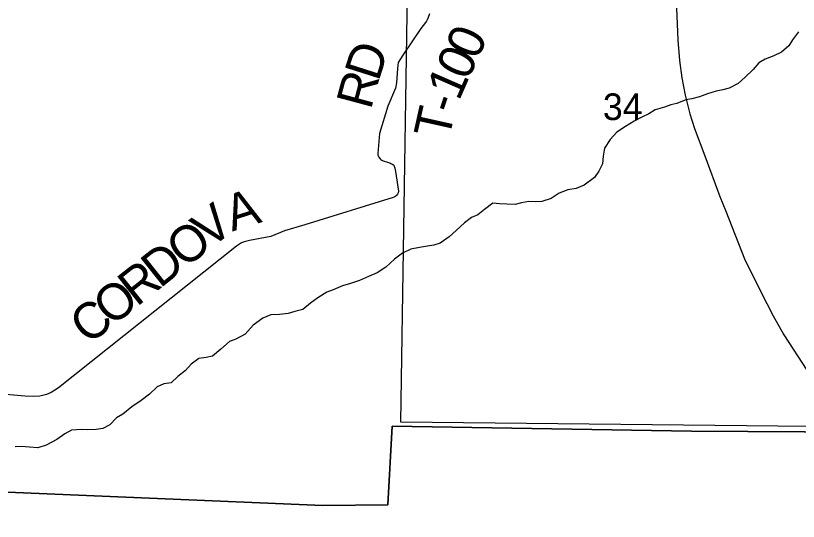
# Model space of a CAD drawing. Extents: x -7.1 to 34, y 0 to 22.
# Drawn here: x 3.24 to 4.468, y 17.646 to 18.44 of the extents above; entities that cross this region are included whole.
import ezdxf

# ---------------------------------------------------------------- set-up
doc = ezdxf.new("R2010")
doc.units = 0
for name, color, linetype in [('GM_X_Minor_River', 7, 'Continuous'), ('GM_X_Section', 7, 'Continuous'), ('GM_X_Section_Text', 7, 'Continuous'), ('GM_X_State_Route', 7, 'Continuous'), ('GM_X_Township_Road', 7, 'Continuous'), ('GM_X_Township_Road_Text', 7, 'Continuous'), ('SH_Cut_Line', 7, 'Continuous')]:
    doc.layers.add(name, color=color, linetype=linetype)

msp = doc.modelspace()

# ---------------------------------------------------------------- linework, layer by layer
at = {"layer": 'GM_X_Minor_River'}
for points in [[(4.4682, 18.4143), (4.4588, 18.4017), (4.4528, 18.3922), (4.4411, 18.3822), (4.4294, 18.3764), (4.4158, 18.3713), (4.4055, 18.3656), (4.3969, 18.3552), (4.3841, 18.3434), (4.3732, 18.3334), (4.3592, 18.3257), (4.3493, 18.3233), (4.3387, 18.3213), (4.3254, 18.3171), (4.3129, 18.3124), (4.3008, 18.3093), (4.2913, 18.3077), (4.2773, 18.3018), (4.2679, 18.2995), (4.2576, 18.296), (4.2432, 18.2917), (4.2334, 18.2855), (4.2224, 18.2805), (4.21, 18.2739), (4.1963, 18.2658), (4.1828, 18.257), (4.1726, 18.2451), (4.1636, 18.2318), (4.1614, 18.2189), (4.1604, 18.2071), (4.1548, 18.1956), (4.1477, 18.1857), (4.1318, 18.1738), (4.1189, 18.1684), (4.106, 18.1664), (4.0924, 18.1609), (4.0799, 18.1529), (4.0652, 18.1482), (4.0557, 18.1473), (4.0447, 18.148), (4.0333, 18.1456), (4.0234, 18.1433), (4.0105, 18.1435), (3.9987, 18.1442), (3.9885, 18.1452), (3.9753, 18.1353), (3.9647, 18.1272), (3.9548, 18.1229), (3.9439, 18.1145), (3.9311, 18.1026), (3.9198, 18.0927), (3.9058, 18.0823), (3.896, 18.0792), (3.8857, 18.0779), (3.8732, 18.0759), (3.8599, 18.0732), (3.8467, 18.067), (3.8342, 18.0574), (3.8207, 18.0447), (3.8071, 18.0359), (3.7934, 18.0301), (3.7791, 18.0239), (3.7651, 18.0192), (3.7525, 18.0153), (3.7378, 18.0091), (3.7279, 18.0056), (3.714, 17.9967), (3.7026, 17.9883), (3.6902, 17.9783), (3.6777, 17.9752), (3.6671, 17.972), (3.6538, 17.9704), (3.6401, 17.9699), (3.6273, 17.9645), (3.6122, 17.9537), (3.5997, 17.9396), (3.5854, 17.9318), (3.5751, 17.9283), (3.5616, 17.9161), (3.5484, 17.9049), (3.5385, 17.903), (3.5271, 17.9014), (3.515, 17.8925), (3.506, 17.8826), (3.4943, 17.873), (3.4838, 17.8634)], [(3.4838, 17.8634), (3.4724, 17.8614), (3.4618, 17.8567), (3.4497, 17.8456), (3.4369, 17.8357), (3.4222, 17.8257), (3.4078, 17.8141), (3.398, 17.8084), (3.3875, 17.7973), (3.3765, 17.7915), (3.3663, 17.7899), (3.3526, 17.7894), (3.3431, 17.7897), (3.3275, 17.7891), (3.3169, 17.783), (3.3045, 17.7745), (3.2878, 17.7656), (3.2746, 17.7614), (3.2617, 17.762), (3.2487, 17.763), (3.2389, 17.7626)]]:
    msp.add_lwpolyline(points, dxfattribs=at)
at = {"layer": 'GM_X_Section'}
msp.add_lwpolyline([(3.8597, 18.828), (4.6987, 18.8125), (4.6817, 17.7925), (3.8439, 17.8017), (3.8583, 18.7127)], close=True, dxfattribs=at)
at = {"layer": 'GM_X_State_Route'}
msp.add_lwpolyline([(4.2752, 18.4883), (4.2777, 18.427), (4.2786, 18.4011), (4.2812, 18.3691), (4.2851, 18.3419), (4.2904, 18.3149), (4.2973, 18.2856), (4.3049, 18.2625), (4.3209, 18.2197), (4.3448, 18.1556), (4.354, 18.1326), (4.3834, 18.058), (4.4082, 18.007), (4.428, 17.9686), (4.4452, 17.9387), (4.4811, 17.883)], dxfattribs=at)
at = {"layer": 'GM_X_Township_Road'}
for points in [[(3.0659, 17.6986), (3.7215, 17.6707), (3.8238, 17.6717), (3.8304, 17.7952), (4.3, 17.7873), (4.5657, 17.7857), (4.7094, 17.7848), (5.0443, 17.7832), (5.0544, 17.7831), (5.1115, 17.7819), (5.5047, 17.7737), (5.7514, 17.7685), (6.1904, 17.7592), (6.3575, 17.7557), (6.7118, 17.7486), (6.7254, 18.1319), (6.7433, 18.7732), (6.7479, 19.0295), (6.7613, 19.7723), (6.7882, 20.743), (6.7921, 20.9), (2.1, 20.9)], [(3.8889, 18.4424), (3.887, 18.437), (3.8854, 18.4334), (3.8843, 18.4312), (3.8827, 18.4291), (3.8755, 18.4196), (3.8473, 18.3776), (3.8399, 18.3661), (3.8389, 18.3566), (3.8374, 18.3345), (3.8356, 18.3257), (3.8235, 18.2978), (3.8105, 18.2546), (3.808, 18.2234), (3.8082, 18.2207), (3.8085, 18.2197), (3.8095, 18.2177), (3.8116, 18.215), (3.8125, 18.2141), (3.8143, 18.2128), (3.8162, 18.2117), (3.8229, 18.2096), (3.8249, 18.2091)], [(3.8249, 18.2091), (3.8268, 18.2085), (3.8286, 18.2078), (3.83, 18.207), (3.8314, 18.2061), (3.8324, 18.2053), (3.8329, 18.2047), (3.8334, 18.204), (3.8338, 18.2032), (3.8347, 18.2002), (3.8356, 18.1953), (3.8403, 18.1642), (3.8398, 18.1618), (3.8388, 18.1593), (3.8374, 18.1572), (3.8349, 18.1555), (3.8321, 18.1542), (3.6937, 18.1111), (3.6615, 18.1018), (3.64, 18.093), (3.6065, 18.0867), (3.5982, 18.0847), (3.5943, 18.083), (3.5861, 18.0776), (3.3072, 17.8556), (3.2952, 17.8478), (3.2882, 17.8448), (3.2821, 17.8433), (3.2776, 17.8422), (3.2675, 17.8416), (3.2545, 17.8421), (3.1086, 17.855)], [(6.7058, 17.2839), (6.7118, 17.7486), (6.3575, 17.7557), (6.1904, 17.7592), (5.7514, 17.7685), (5.5047, 17.7737), (5.1115, 17.7819), (5.0544, 17.7831), (5.0443, 17.7832), (4.7094, 17.7848), (4.5657, 17.7857), (4.3, 17.7873), (3.8304, 17.7952), (3.8238, 17.6717), (3.7215, 17.6707), (3.0659, 17.6986), (2.7886, 17.7105), (2.5551, 17.7155), (2.1, 17.7253), (2.1, 14.1)]]:
    msp.add_lwpolyline(points, dxfattribs=at)
at = {"layer": 'SH_Cut_Line'}
for points in [[(8.9, 17.7079), (8.9, 20.9), (2.1, 20.9), (2.1, 17.7253), (2.5551, 17.7155), (2.7886, 17.7105), (3.0659, 17.6986), (3.7215, 17.6707), (3.8238, 17.6717), (3.8304, 17.7952), (4.3, 17.7873), (4.5657, 17.7857), (4.7094, 17.7848), (5.0443, 17.7832), (5.0544, 17.7831), (5.1115, 17.7819), (5.5047, 17.7737), (5.7514, 17.7685), (6.1904, 17.7592), (6.3575, 17.7557), (6.7118, 17.7486), (7.7202, 17.7285), (8.4472, 17.7189), (8.6668, 17.7136)], [(2.1, 17.7253), (2.1, 14.1), (8.9, 14.1), (8.9, 17.7079), (8.6668, 17.7136), (8.4472, 17.7189), (7.7202, 17.7285), (6.7118, 17.7486), (6.3575, 17.7557), (6.1904, 17.7592), (5.7514, 17.7685), (5.5047, 17.7737), (5.1115, 17.7819), (5.0544, 17.7831), (5.0443, 17.7832), (4.7094, 17.7848), (4.5657, 17.7857), (4.3, 17.7873), (3.8304, 17.7952), (3.8238, 17.6717), (3.7215, 17.6707), (3.0659, 17.6986), (2.7886, 17.7105), (2.5551, 17.7155)]]:
    msp.add_lwpolyline(points, close=True, dxfattribs=at)

# ---------------------------------------------------------------- texts
at = {"layer": 'GM_X_Section_Text'}
msp.add_text('34', height=0.04186, rotation=0, dxfattribs=at).set_placement((4.1611, 18.2758))
at = {"layer": 'GM_X_Township_Road_Text'}
for s, rotation, p in [('0', 65.7696, (3.964, 18.3686)), ('D', 72.258, (3.8089, 18.335)), ('0', 65.0631, (3.9489, 18.3362)), ('R', 74.9532, (3.797, 18.2907)), ('1', 66.4396, (3.9351, 18.3045)), ('-', 71.7057, (3.9282, 18.2836)), ('T', 77.4456, (3.9194, 18.2436)), ('A', 17.6407, (3.5794, 18.1006)), ('V', 37.3413, (3.5442, 18.0727)), ('O', 38.4365, (3.5053, 18.0418)), ('D', 38.4455, (3.4661, 18.0107)), ('R', 38.4454, (3.4296, 17.9817)), ('O', 38.4445, (3.3904, 17.9506)), ('C', 38.4462, (3.3539, 17.9216))]:
    msp.add_text(s, height=0.0568, rotation=rotation, dxfattribs=at).set_placement(p)

doc.saveas('drawing.dxf')
